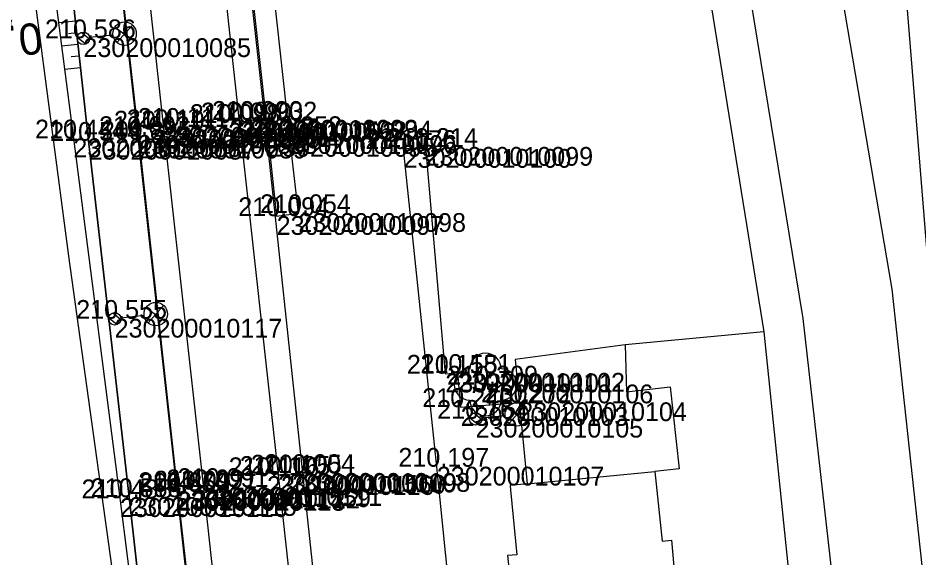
# Model space of a CAD drawing. Extents: x -563148 to -561712, y -1182311 to -1179502.
# Drawn here: x -562696.1 to -562638.6, y -1180141.3 to -1180106.8 of the extents above; entities that cross this region are included whole.
import ezdxf

# ---------------------------------------------------------------- set-up
doc = ezdxf.new("R2010")
doc.units = 0
for name, color, linetype in [('Vrstva 1', 7, 'Continuous'), ('Vrstva 14', 7, 'Continuous'), ('Vrstva 16', 7, 'Continuous'), ('Vrstva 25', 7, 'Continuous'), ('Vrstva 4', 7, 'Continuous'), ('Vrstva 48', 7, 'Continuous'), ('Vrstva 49', 7, 'Continuous'), ('Vrstva 50', 7, 'Continuous'), ('Vrstva 53', 7, 'Continuous'), ('Vrstva 55', 7, 'Continuous'), ('Vrstva 56', 7, 'Continuous'), ('Vrstva 60', 7, 'Continuous'), ('Vrstva 61', 7, 'Continuous')]:
    doc.layers.add(name, color=color, linetype=linetype)

msp = doc.modelspace()

# ---------------------------------------------------------------- linework, layer by layer
at = {"layer": 'Vrstva 1'}
for points in [[(-562684.601, -1180089.769), (-562682.005, -1180113.42), (-562679.522, -1180136.019), (-562677.965, -1180150.235), (-562677.074, -1180158.297), (-562674.316, -1180183.276), (-562671.872, -1180205.481), (-562669.181, -1180229.918), (-562666.546, -1180253.83), (-562663.377, -1180282.454), (-562660.875, -1180304.41), (-562657.731, -1180328.532), (-562653.091, -1180356.898), (-562648.135, -1180380.434), (-562641.987, -1180404.158), (-562632.843, -1180433.404), (-562624.351, -1180457.448), (-562616.401, -1180478.664), (-562609.262, -1180497.358), (-562601.11, -1180519.011), (-562593.203, -1180541.01)], [(-562689.436, -1180090.302), (-562686.841, -1180113.856), (-562684.304, -1180136.877), (-562682.795, -1180150.556), (-562681.889, -1180158.806), (-562679.159, -1180183.555), (-562676.699, -1180205.887), (-562674.017, -1180230.17), (-562671.316, -1180254.475), (-562668.194, -1180282.592), (-562665.588, -1180304.975), (-562662.339, -1180329.404), (-562657.661, -1180357.664), (-562652.654, -1180381.236), (-562646.28, -1180405.627), (-562637.045, -1180434.799), (-562628.494, -1180458.746), (-562620.522, -1180479.901), (-562613.348, -1180498.592), (-562605.093, -1180520.3), (-562597.152, -1180542.181)]]:
    msp.add_lwpolyline(points, dxfattribs=at)
at = {"layer": 'Vrstva 14'}
for points in [[(-562708.479, -1179929.163), (-562709.809, -1179929.515), (-562709.063, -1179932.483), (-562703.908, -1179952.98), (-562698.53, -1179977.594), (-562694.4, -1179999.838), (-562690.742, -1180023.288), (-562687.628, -1180047.308), (-562685.267, -1180067.341), (-562682.923, -1180089.427), (-562680.167, -1180114.478), (-562679.62, -1180119.474), (-562678.231, -1180119.285), (-562678.795, -1180114.297), (-562681.543, -1180089.232), (-562683.879, -1180067.219), (-562686.248, -1180047.116), (-562689.374, -1180023.01), (-562693.012, -1179999.725), (-562697.19, -1179977.322), (-562702.554, -1179952.668), (-562707.742, -1179932.132), (-562708.479, -1179929.163)], [(-562704.457, -1180009.876), (-562702.908, -1180009.65), (-562701.375, -1180009.384), (-562699.101, -1180024.192), (-562695.974, -1180047.96), (-562693.659, -1180067.754), (-562691.151, -1180090.53), (-562688.519, -1180114.291), (-562686.007, -1180137.055), (-562684.701, -1180148.931), (-562683.81, -1180156.835), (-562683.773, -1180157.201), (-562683.577, -1180157.173), (-562683.179, -1180160.788), (-562686.398, -1180161.15), (-562686.854, -1180157.198), (-562687.714, -1180149.264), (-562689.044, -1180137.442), (-562691.641, -1180114.662), (-562694.248, -1180090.83), (-562696.771, -1180068.075), (-562699.07, -1180048.328), (-562702.18, -1180024.606), (-562704.457, -1180009.876)]]:
    msp.add_lwpolyline(points, dxfattribs=at)
at = {"layer": 'Vrstva 16'}
msp.add_lwpolyline([(-562663.361, -1180165.832), (-562666.49, -1180166.14), (-562667.056, -1180159.137), (-562675.387, -1180159.927), (-562675.787, -1180156.315), (-562667.368, -1180155.516), (-562669.388, -1180135.498), (-562671.504, -1180115.184), (-562670.109, -1180115.053), (-562668.844, -1180129.548), (-562668.071, -1180129.501), (-562667.864, -1180131.684), (-562664.117, -1180131.383)], dxfattribs=at)
at = {"layer": 'Vrstva 25'}
for p, q in [((-562689.955, -1180107.402), (-562688.734, -1180108.258)), ((-562688.834, -1180107.264), (-562689.831, -1180108.373)), ((-562692.356, -1180108.025), (-562691.805, -1180108.467)), ((-562692.09, -1180107.726), (-562691.573, -1180108.141)), ((-562690.079, -1180107.897), (-562691.57, -1180108.061)), ((-562687.964, -1180125.331), (-562686.738, -1180126.182)), ((-562686.843, -1180125.188), (-562687.835, -1180126.301)), ((-562690.361, -1180125.964), (-562689.808, -1180126.405)), ((-562690.097, -1180125.665), (-562689.577, -1180126.077)), ((-562688.085, -1180125.827), (-562689.576, -1180125.997)), ((-562664.893, -1180131.741), (-562663.676, -1180132.604)), ((-562663.77, -1180131.609), (-562664.773, -1180132.713)), ((-562667.297, -1180132.352), (-562666.747, -1180132.797)), ((-562667.029, -1180132.054), (-562666.514, -1180132.472)), ((-562665.019, -1180132.236), (-562666.511, -1180132.392))]:
    msp.add_line(p, q, dxfattribs=at)
for centre, radius in [((-562689.336, -1180107.813), 0.749), ((-562691.968, -1180108.104), 0.4), ((-562687.342, -1180125.739), 0.749), ((-562689.973, -1180126.042), 0.4), ((-562664.275, -1180132.156), 0.749), ((-562666.909, -1180132.433), 0.4)]:
    msp.add_circle(centre, radius, dxfattribs=at)
at = {"layer": 'Vrstva 4'}
for points in [[(-562683.721, -1180156.67), (-562685.937, -1180137.111), (-562688.396, -1180114.587), (-562691.083, -1180090.754), (-562693.511, -1180068.129), (-562695.855, -1180048.009), (-562699.08, -1180023.859), (-562701.311, -1180009.058), (-562702.782, -1180000.957), (-562706.808, -1179979.526), (-562712.563, -1179954.534), (-562717.351, -1179935.12), (-562723.98, -1179911.208), (-562730.867, -1179887.274)], [(-562694.597, -1179999.064), (-562690.854, -1180023.004), (-562687.785, -1180047.019), (-562685.386, -1180067.45), (-562683.032, -1180089.38), (-562680.384, -1180113.364), (-562677.963, -1180135.901), (-562675.805, -1180156.217)]]:
    msp.add_lwpolyline(points, dxfattribs=at)
at = {"layer": 'Vrstva 48'}
for p, q in [((-562692.478, -1180107.009), (-562693.558, -1180107.127)), ((-562692.397, -1180107.754), (-562692.929, -1180107.813)), ((-562692.315, -1180108.5), (-562693.366, -1180108.615)), ((-562692.234, -1180109.246), (-562692.752, -1180109.302)), ((-562692.152, -1180109.991), (-562693.174, -1180110.103))]:
    msp.add_line(p, q, dxfattribs=at)
at = {"layer": 'Vrstva 49'}
for points in [[(-562695.71, -1180085.266), (-562695.985, -1180088.311), (-562692.606, -1180114.511), (-562689.631, -1180137.512), (-562688.165, -1180149.149), (-562686.617, -1180161.621), (-562684.519, -1180163.108), (-562684.354, -1180163.85)], [(-562695.71, -1180085.266), (-562694.248, -1180090.83), (-562691.641, -1180114.662), (-562689.044, -1180137.442), (-562687.714, -1180149.264), (-562686.854, -1180157.198), (-562686.398, -1180161.15), (-562684.519, -1180163.108)]]:
    msp.add_lwpolyline(points, dxfattribs=at)
at = {"layer": 'Vrstva 50'}
msp.add_line((-562666.338, -1180130.242), (-562666.196, -1180130.242), dxfattribs=at)
for centre, start, end in [((-562666.278, -1180129.24), 0, 180), ((-562667.278, -1180130.24), 90, 270), ((-562665.278, -1180130.24), 270, 90), ((-562666.278, -1180131.24), 180, 0)]:
    msp.add_arc(centre, 1, start, end, dxfattribs=at)
at = {"layer": 'Vrstva 53'}
for p, q in [((-562666.05, -1180017.58), (-562648.5, -1180126.87)), ((-562692.89, -1180122.04), (-562700.4, -1180065.16)), ((-562687.63, -1180159.95), (-562692.89, -1180122.04)), ((-562648.5, -1180126.87), (-562657.35, -1180127.71)), ((-562648.5, -1180126.87), (-562646.5, -1180146.22)), ((-562657.35, -1180127.71), (-562664.39, -1180128.64)), ((-562664.39, -1180128.64), (-562663.61, -1180136.59)), ((-562663.61, -1180136.59), (-562664.7, -1180136.69)), ((-562664.7, -1180136.69), (-562664.67, -1180136.97)), ((-562664.67, -1180136.97), (-562664.27, -1180141.13)), ((-562664.27, -1180141.13), (-562664.86, -1180141.18)), ((-562664.86, -1180141.18), (-562664.22, -1180147.77))]:
    msp.add_line(p, q, dxfattribs=at)
at = {"layer": 'Vrstva 55'}
msp.add_line((-562641.2, -1180083.09), (-562637.95, -1180123.37), dxfattribs=at)
at = {"layer": 'Vrstva 56'}
for p, q in [((-562659.01, -1180014.55), (-562640.31, -1180124.15)), ((-562645.98, -1180126.03), (-562663.84, -1180016.63)), ((-562640.31, -1180124.15), (-562633.56, -1180186.11)), ((-562639.33, -1180184.45), (-562645.98, -1180126.03)), ((-562657.35, -1180127.71), (-562657.26, -1180130.7)), ((-562657.26, -1180130.7), (-562654.47, -1180130.4)), ((-562654.47, -1180130.4), (-562653.91, -1180135.63)), ((-562663.61, -1180136.59), (-562655.45, -1180135.81)), ((-562653.91, -1180135.63), (-562655.45, -1180135.81)), ((-562655.45, -1180135.81), (-562654.98, -1180140.25)), ((-562654.98, -1180140.25), (-562654.39, -1180140.2)), ((-562654.39, -1180140.2), (-562653.82, -1180146.69))]:
    msp.add_line(p, q, dxfattribs=at)
at = {"layer": 'Vrstva 60'}
for p, q in [((-562691.968, -1180108.104), (-562691.968, -1180108.104)), ((-562681.293, -1180113.321), (-562681.293, -1180113.321)), ((-562680.384, -1180113.364), (-562680.384, -1180113.364)), ((-562687.557, -1180113.942), (-562687.557, -1180113.942)), ((-562686.841, -1180113.856), (-562686.841, -1180113.856)), ((-562686.126, -1180113.769), (-562686.126, -1180113.769)), ((-562682.717, -1180113.519), (-562682.717, -1180113.519)), ((-562682.005, -1180113.42), (-562682.005, -1180113.42)), ((-562692.606, -1180114.511), (-562692.606, -1180114.511)), ((-562688.519, -1180114.291), (-562688.519, -1180114.291)), ((-562680.167, -1180114.478), (-562680.167, -1180114.478)), ((-562678.795, -1180114.297), (-562678.795, -1180114.297)), ((-562691.641, -1180114.662), (-562691.641, -1180114.662)), ((-562688.396, -1180114.587), (-562688.396, -1180114.587)), ((-562670.109, -1180115.053), (-562670.109, -1180115.053)), ((-562671.504, -1180115.184), (-562671.504, -1180115.184)), ((-562679.62, -1180119.474), (-562679.62, -1180119.474)), ((-562678.231, -1180119.285), (-562678.231, -1180119.285)), ((-562689.973, -1180126.042), (-562689.973, -1180126.042)), ((-562668.071, -1180129.501), (-562668.071, -1180129.501)), ((-562668.844, -1180129.548), (-562668.844, -1180129.548)), ((-562666.267, -1180130.242), (-562666.267, -1180130.242)), ((-562667.864, -1180131.684), (-562667.864, -1180131.684)), ((-562664.117, -1180131.383), (-562664.117, -1180131.383)), ((-562666.909, -1180132.433), (-562666.909, -1180132.433)), ((-562669.388, -1180135.498), (-562669.388, -1180135.498)), ((-562680.234, -1180136.101), (-562680.234, -1180136.101)), ((-562679.522, -1180136.019), (-562679.522, -1180136.019)), ((-562678.81, -1180135.937), (-562678.81, -1180135.937)), ((-562677.963, -1180135.901), (-562677.963, -1180135.901)), ((-562685.018, -1180136.957), (-562685.018, -1180136.957)), ((-562684.304, -1180136.877), (-562684.304, -1180136.877)), ((-562683.59, -1180136.798), (-562683.59, -1180136.798)), ((-562689.631, -1180137.512), (-562689.631, -1180137.512)), ((-562689.044, -1180137.442), (-562689.044, -1180137.442)), ((-562686.007, -1180137.055), (-562686.007, -1180137.055)), ((-562685.937, -1180137.111), (-562685.937, -1180137.111))]:
    msp.add_line(p, q, dxfattribs=at)

# ---------------------------------------------------------------- texts
at = {"layer": 'Vrstva 48'}
msp.add_text('0,1', height=2, rotation=187.34884, dxfattribs=at).set_placement((-562694.743, -1180107.069))
at = {"layer": 'Vrstva 60'}
for s, p in [('230200010085', (-562691.968, -1180109.304)), ('230200011562', (-562682.005, -1180114.62)), ('230200010093', (-562681.293, -1180114.521)), ('230200010094', (-562680.384, -1180114.564)), ('230200010090', (-562687.557, -1180115.142)), ('230200011561', (-562686.841, -1180115.056)), ('230200010091', (-562686.126, -1180114.969)), ('230200010092', (-562682.717, -1180114.719)), ('230200010086', (-562692.606, -1180115.711)), ('230200010088', (-562688.519, -1180115.491)), ('230200010095', (-562680.167, -1180115.678)), ('230200010096', (-562678.795, -1180115.497)), ('230200010087', (-562691.641, -1180115.862)), ('230200010089', (-562688.396, -1180115.787)), ('230200010099', (-562670.109, -1180116.253)), ('230200010100', (-562671.504, -1180116.384)), ('230200010097', (-562679.62, -1180120.674)), ('230200010098', (-562678.231, -1180120.485)), ('230200010117', (-562689.973, -1180127.242)), ('230200010102', (-562668.071, -1180130.701)), ('230200010101', (-562668.844, -1180130.748)), ('230200010106', (-562666.267, -1180131.442)), ('230200010103', (-562667.864, -1180132.884)), ('230200010104', (-562664.117, -1180132.583)), ('230200010105', (-562666.909, -1180133.633)), ('230200010107', (-562669.388, -1180136.698)), ('230200010110', (-562680.234, -1180137.301)), ('230200011560', (-562679.522, -1180137.219)), ('230200010109', (-562678.81, -1180137.137)), ('230200010108', (-562677.963, -1180137.101)), ('230200010112', (-562685.018, -1180138.157)), ('230200011559', (-562684.304, -1180138.077)), ('230200010111', (-562683.59, -1180137.998)), ('230200010116', (-562689.631, -1180138.712)), ('230200010115', (-562689.044, -1180138.642)), ('230200010114', (-562686.007, -1180138.255)), ('230200010113', (-562685.937, -1180138.311))]:
    msp.add_text(s, height=1.2, dxfattribs=at).set_placement(p)
at = {"layer": 'Vrstva 61'}
for s, p in [('210.586', (-562694.42, -1180108.104)), ('210.090', (-562684.456, -1180113.42)), ('210.090', (-562683.744, -1180113.321)), ('209.932', (-562682.832, -1180113.364)), ('210.119', (-562690.011, -1180113.942)), ('210.111', (-562689.198, -1180113.856)), ('210.111', (-562688.483, -1180113.769)), ('210.098', (-562685.171, -1180113.519)), ('210.444', (-562695.057, -1180114.511)), ('210.692', (-562690.967, -1180114.291)), ('209.895', (-562690.852, -1180114.587)), ('210.376', (-562682.619, -1180114.478)), ('210.252', (-562681.243, -1180114.297)), ('210.544', (-562694.092, -1180114.662)), ('210.176', (-562673.956, -1180115.184)), ('210.214', (-562672.56, -1180115.053)), ('210.094', (-562682.071, -1180119.474)), ('210.054', (-562680.682, -1180119.285)), ('210.555', (-562692.429, -1180126.042)), ('210.155', (-562671.3, -1180129.548)), ('210.181', (-562670.428, -1180129.501)), ('210.309', (-562668.721, -1180130.242)), ('210.240', (-562670.315, -1180131.684)), ('210.272', (-562666.565, -1180131.383)), ('210.164', (-562669.36, -1180132.433)), ('210.197', (-562671.84, -1180135.498)), ('210.116', (-562682.686, -1180136.101)), ('210.105', (-562681.978, -1180136.019)), ('210.105', (-562681.266, -1180135.937)), ('210.004', (-562680.414, -1180135.901)), ('210.092', (-562687.466, -1180136.957)), ('210.091', (-562686.661, -1180136.877)), ('210.091', (-562685.947, -1180136.798)), ('210.488', (-562692.085, -1180137.512)), ('210.558', (-562691.498, -1180137.442)), ('210.674', (-562688.458, -1180137.055)), ('209.853', (-562688.389, -1180137.111))]:
    msp.add_text(s, height=1.2, dxfattribs=at).set_placement(p)

doc.saveas('drawing.dxf')
